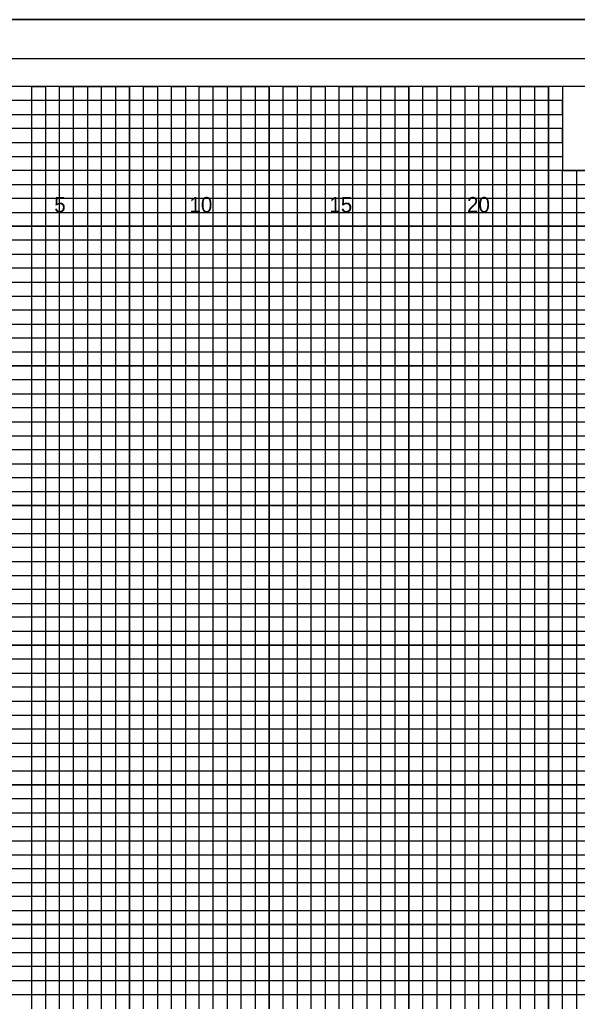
# Model space of a CAD drawing. Extents: x -4 to 103, y -2 to 209.
# Drawn here: x 54.82 to 74.78, y 103.08 to 138.22 of the extents above; entities that cross this region are included whole.
import ezdxf

# ---------------------------------------------------------------- set-up
doc = ezdxf.new("R2010")
doc.units = 0
for name, color, linetype in [('Old_Level_10', 7, 'Continuous'), ('Old_Level_16', 7, 'Continuous'), ('Old_Level_3', 7, 'Continuous'), ('Old_Level_4', 7, 'Continuous'), ('Old_Level_5', 7, 'Continuous'), ('Old_Level_6', 7, 'Continuous'), ('Old_Level_8', 7, 'Continuous'), ('Prop Dimension', 7, 'Continuous')]:
    doc.layers.add(name, color=color, linetype=linetype)

msp = doc.modelspace()

# ---------------------------------------------------------------- linework, layer by layer
at = {"layer": 'Old_Level_10'}
for p, q in [((56.25, 70.825), (56.25, 135.825)), ((58.75, 70.825), (58.75, 135.825)), ((61.25, 70.825), (61.25, 135.825)), ((63.75, 70.825), (63.75, 135.825)), ((66.25, 70.825), (66.25, 135.825)), ((68.75, 70.825), (68.75, 135.825)), ((71.25, 70.825), (71.25, 135.825)), ((73.75, 70.825), (73.75, 135.825)), ((0, 133.325), (74.25, 133.325)), ((0, 130.825), (102.5, 130.825)), ((0, 128.325), (102.5, 128.325)), ((0, 125.825), (102.5, 125.825)), ((0, 123.325), (102.5, 123.325)), ((0, 120.825), (102.5, 120.825)), ((0, 118.325), (102.5, 118.325)), ((0, 115.825), (102.5, 115.825)), ((0, 113.325), (102.5, 113.325)), ((0, 110.825), (102.5, 110.825)), ((0, 108.325), (102.5, 108.325)), ((0, 105.825), (102.5, 105.825)), ((0, 103.325), (102.5, 103.325))]:
    msp.add_line(p, q, dxfattribs=at)
at = {"layer": 'Old_Level_3'}
msp.add_line((-3.5, 138.225), (103.4, 138.225), dxfattribs=at)
at = {"layer": 'Old_Level_4'}
msp.add_lwpolyline([(103, 136.825), (-2.8, 136.825), (-2.8, 69.825), (103, 69.825)], close=True, dxfattribs=at)
at = {"layer": 'Old_Level_5'}
msp.add_lwpolyline([(103.4, 138.225), (-3.5, 138.225), (-3.5, 68.4), (103.4, 68.4)], close=True, dxfattribs=at)
at = {"layer": 'Old_Level_6'}
for points in [[(102.5, 135.825), (0, 135.825), (0, 70.825), (102.5, 70.825)], [(83.75, 135.825), (74.25, 135.825), (74.25, 132.825), (83.75, 132.825)]]:
    msp.add_lwpolyline(points, close=True, dxfattribs=at)
at = {"layer": 'Old_Level_8'}
for points in [[(56.25, 70.825), (56.25, 135.825), (58.75, 135.825), (58.75, 70.825)], [(61.25, 70.825), (61.25, 135.825), (63.75, 135.825), (63.75, 70.825)], [(66.25, 70.825), (66.25, 135.825), (68.75, 135.825), (68.75, 70.825)], [(71.25, 70.825), (71.25, 135.825), (73.75, 135.825), (73.75, 70.825)], [(0, 133.325), (74.25, 133.325)], [(0, 128.325), (102.5, 128.325), (102.5, 130.825), (0, 130.825)], [(0, 123.325), (102.5, 123.325), (102.5, 125.825), (0, 125.825)], [(0, 118.325), (102.5, 118.325), (102.5, 120.825), (0, 120.825)], [(0, 113.325), (102.5, 113.325), (102.5, 115.825), (0, 115.825)], [(0, 108.325), (102.5, 108.325), (102.5, 110.825), (0, 110.825)], [(0, 103.325), (102.5, 103.325), (102.5, 105.825), (0, 105.825)]]:
    msp.add_lwpolyline(points, dxfattribs=at)
at = {"layer": 'Prop Dimension'}
for points in [[(55.25, 70.825), (55.25, 135.825), (55.75, 135.825), (55.75, 70.825)], [(56.75, 70.825), (56.75, 135.825), (57.25, 135.825), (57.25, 70.825)], [(57.75, 70.825), (57.75, 135.825), (58.25, 135.825), (58.25, 70.825)], [(59.25, 70.825), (59.25, 135.825), (59.75, 135.825), (59.75, 70.825)], [(60.25, 70.825), (60.25, 135.825), (60.75, 135.825), (60.75, 70.825)], [(61.75, 70.825), (61.75, 135.825), (62.25, 135.825), (62.25, 70.825)], [(62.75, 70.825), (62.75, 135.825), (63.25, 135.825), (63.25, 70.825)], [(64.25, 70.825), (64.25, 135.825), (64.75, 135.825), (64.75, 70.825)], [(65.25, 70.825), (65.25, 135.825), (65.75, 135.825), (65.75, 70.825)], [(66.75, 70.825), (66.75, 135.825), (67.25, 135.825), (67.25, 70.825)], [(67.75, 70.825), (67.75, 135.825), (68.25, 135.825), (68.25, 70.825)], [(69.25, 70.825), (69.25, 135.825)], [(69.25, 135.825), (69.75, 135.825), (69.75, 70.825)], [(70.25, 70.825), (70.25, 135.825), (70.75, 135.825), (70.75, 70.825)], [(71.75, 70.825), (71.75, 135.825), (72.25, 135.825), (72.25, 70.825)], [(72.75, 70.825), (72.75, 135.825), (73.25, 135.825), (73.25, 70.825)], [(0, 132.825), (0, 133.825), (74.25, 133.825), (74.25, 134.325), (0, 134.325), (0, 134.825), (74.25, 134.825), (74.25, 135.325), (0, 135.325)], [(0, 132.325), (102.5, 132.325), (102.5, 132.825), (0, 132.825)], [(74.25, 70.825), (74.25, 132.825), (74.75, 132.825), (74.75, 70.825)], [(0, 131.325), (102.5, 131.325), (102.5, 131.825), (0, 131.825)], [(0, 129.825), (102.5, 129.825), (102.5, 130.325), (0, 130.325)], [(0, 128.825), (102.5, 128.825), (102.5, 129.325), (0, 129.325)], [(0, 127.325), (102.5, 127.325), (102.5, 127.825), (0, 127.825)], [(0, 126.325), (102.5, 126.325), (102.5, 126.825), (0, 126.825)], [(0, 124.825), (102.5, 124.825), (102.5, 125.325), (0, 125.325)], [(0, 123.825), (102.5, 123.825), (102.5, 124.325), (0, 124.325)], [(0, 122.325), (102.5, 122.325), (102.5, 122.825), (0, 122.825)], [(0, 121.325), (102.5, 121.325), (102.5, 121.825), (0, 121.825)], [(0, 119.825), (102.5, 119.825), (102.5, 120.325), (0, 120.325)], [(0, 118.825), (102.5, 118.825), (102.5, 119.325), (0, 119.325)], [(0, 117.325), (102.5, 117.325), (102.5, 117.825), (0, 117.825)], [(0, 116.325), (102.5, 116.325), (102.5, 116.825), (0, 116.825)], [(0, 114.825), (102.5, 114.825), (102.5, 115.325), (0, 115.325)], [(0, 113.825), (102.5, 113.825), (102.5, 114.325), (0, 114.325)], [(0, 112.325), (102.5, 112.325), (102.5, 112.825), (0, 112.825)], [(0, 111.325), (102.5, 111.325), (102.5, 111.825), (0, 111.825)], [(0, 109.825), (102.5, 109.825), (102.5, 110.325), (0, 110.325)], [(0, 108.825), (102.5, 108.825), (102.5, 109.325), (0, 109.325)], [(0, 107.325), (102.5, 107.325), (102.5, 107.825), (0, 107.825)], [(0, 106.325), (102.5, 106.325), (102.5, 106.825), (0, 106.825)], [(0, 104.825), (102.5, 104.825), (102.5, 105.325), (0, 105.325)], [(0, 103.825), (102.5, 103.825), (102.5, 104.325), (0, 104.325)]]:
    msp.add_lwpolyline(points, dxfattribs=at)

# ---------------------------------------------------------------- texts
at = {"layer": 'Old_Level_16'}
for s, p in [('5', (56.0574, 131.325)), ('10', (60.8971, 131.325)), ('15', (65.9057, 131.325)), ('20', (70.8312, 131.325))]:
    msp.add_text(s, height=0.55, dxfattribs=at).set_placement(p)

doc.saveas('drawing.dxf')
